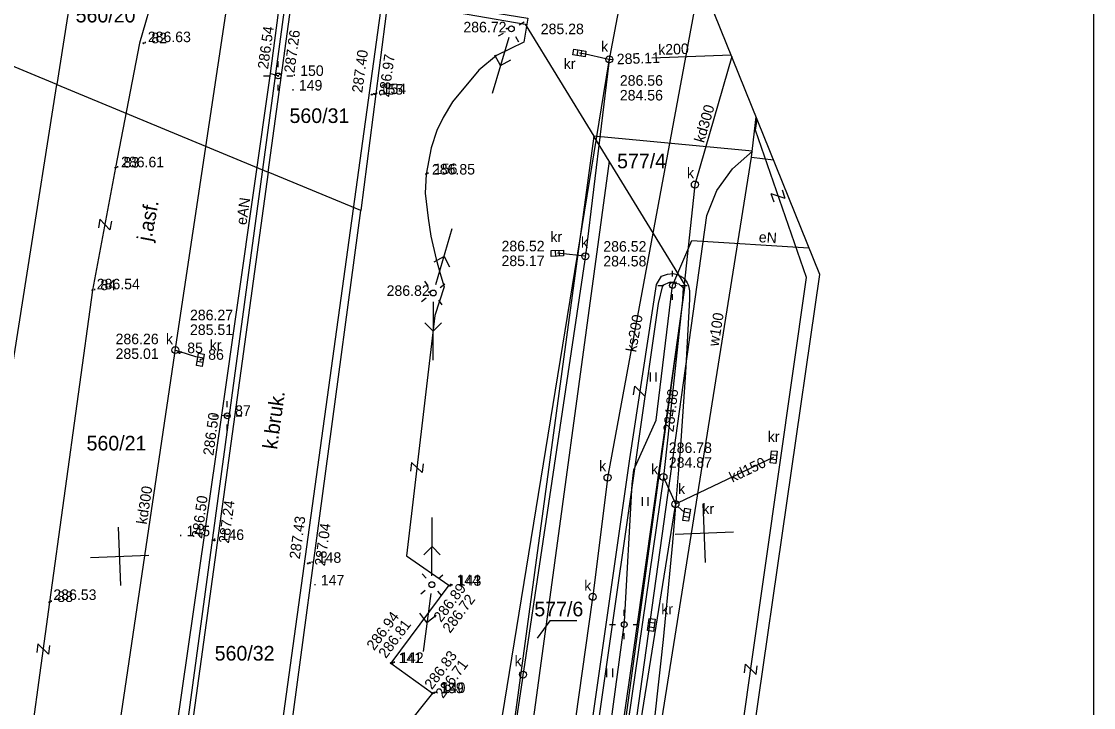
# Model space of a CAD drawing. Extents: x 4632591 to 4651936, y 5351032 to 5369988.
# Drawn here: x 4642775.6 to 4642867.2, y 5360136.4 to 5360195 of the extents above; entities that cross this region are included whole.
import ezdxf

# ---------------------------------------------------------------- set-up
doc = ezdxf.new("R2010")
doc.units = 0
for name, color, linetype in [('EBUPP_312', 7, 'Continuous'), ('EDTTS_991', 7, 'Continuous'), ('EDZPD_211', 7, 'Continuous'), ('EDZPD_219', 7, 'Continuous'), ('SDRPK_422', 7, 'Continuous'), ('SDRPK_423', 7, 'Continuous'), ('SDRPK_432', 7, 'Continuous'), ('SDRPT_450', 7, 'Continuous'), ('SZZTZ_940', 7, 'Continuous'), ('UEEPA_510', 7, 'Continuous'), ('UEEPO_585', 7, 'Continuous'), ('UEETA_515', 7, 'Continuous'), ('UEETA_516', 7, 'Continuous'), ('UKKPA_506', 7, 'Continuous'), ('UKKPA_509', 7, 'Continuous'), ('UKKPO_582', 7, 'Continuous'), ('UWWPO_581', 7, 'Continuous'), ('Warstwa 40', 7, 'Continuous'), ('Warstwa 50', 7, 'Continuous'), ('Warstwa 62', 7, 'Continuous'), ('WUKPS_403', 7, 'Continuous')]:
    doc.layers.add(name, color=color, linetype=linetype)

msp = doc.modelspace()

# ---------------------------------------------------------------- linework, layer by layer
at = {"layer": 'EBUPP_312'}
msp.add_lwpolyline([(4642867.168, 5360325.869), (4642867.168, 5360025.339), (4642701.152, 5360025.339), (4642701.152, 5360349.707), (4642867.168, 5360349.707), (4642867.168, 5360324.166)], dxfattribs=at)
at = {"layer": 'EDTTS_991'}
for p, q in [((4642840.821, 5360179.874), (4642840.576, 5360180.583)), ((4642839.876, 5360179.547), (4642839.631, 5360180.256)), ((4642840.821, 5360179.874), (4642839.631, 5360180.256)), ((4642782.272, 5360178.099), (4642782.133, 5360177.362)), ((4642782.272, 5360178.099), (4642783.116, 5360177.177)), ((4642783.255, 5360177.914), (4642783.116, 5360177.177)), ((4642827.87, 5360163.091), (4642827.983, 5360163.832)), ((4642828.858, 5360162.94), (4642827.983, 5360163.832)), ((4642828.858, 5360162.94), (4642828.972, 5360163.681)), ((4642808.896, 5360157.3), (4642808.808, 5360156.555)), ((4642808.896, 5360157.3), (4642809.801, 5360156.438)), ((4642809.889, 5360157.182), (4642809.801, 5360156.438)), ((4642776.969, 5360141.813), (4642776.868, 5360141.07)), ((4642776.969, 5360141.813), (4642777.859, 5360140.935)), ((4642777.96, 5360141.678), (4642777.859, 5360140.935)), ((4642837.336, 5360139.321), (4642837.442, 5360140.064)), ((4642838.326, 5360139.181), (4642837.442, 5360140.064)), ((4642838.326, 5360139.181), (4642838.432, 5360139.923))]:
    msp.add_line(p, q, dxfattribs=at)
at = {"layer": 'EDZPD_219'}
for p, q in [((4642782.126, 5360212.287), (4642778.595, 5360189.601)), ((4642796.649, 5360182.126), (4642799.275, 5360201.211)), ((4642806.875, 5360196.789), (4642804.574, 5360178.838)), ((4642806.875, 5360196.789), (4642818.602, 5360194.772)), ((4642818.602, 5360194.772), (4642824.477, 5360185.186)), ((4642778.595, 5360189.601), (4642772.763, 5360192.015)), ((4642768.336, 5360124.696), (4642778.595, 5360189.601)), ((4642778.595, 5360189.601), (4642796.649, 5360182.126)), ((4642824.477, 5360185.186), (4642806.059, 5360050.143)), ((4642825.78, 5360183.06), (4642824.477, 5360185.186)), ((4642838.018, 5360183.919), (4642824.477, 5360185.186)), ((4642836.319, 5360182.405), (4642838.018, 5360183.919)), ((4642825.78, 5360183.06), (4642807.62, 5360049.911)), ((4642832.263, 5360172.47), (4642825.78, 5360183.06)), ((4642825.78, 5360183.06), (4642825.78, 5360183.06)), ((4642834.988, 5360180.554), (4642836.319, 5360182.405)), ((4642836.319, 5360182.405), (4642836.319, 5360182.405)), ((4642796.649, 5360182.126), (4642788.376, 5360121.952)), ((4642804.574, 5360178.838), (4642796.649, 5360182.126)), ((4642834.115, 5360178.413), (4642834.988, 5360180.554)), ((4642796.747, 5360120.803), (4642804.574, 5360178.838)), ((4642814.236, 5360035.496), (4642834.115, 5360178.413)), ((4642815.357, 5360048.606), (4642832.263, 5360172.47)), ((4642820.715, 5360143.758), (4642819.624, 5360142.294)), ((4642823.03, 5360143.758), (4642820.715, 5360143.758))]:
    msp.add_line(p, q, dxfattribs=at)
at = {"layer": 'SDRPK_422'}
for points in [[(4642800.957, 5360247.6), (4642789.673, 5360207.012), (4642785.643, 5360193.138), (4642783.61, 5360182.51), (4642781.64, 5360172.03), (4642777.96, 5360145.38), (4642775.66, 5360128.5)], [(4642812.515, 5360206.822), (4642811.234, 5360196.488), (4642818.833, 5360195.279), (4642818.488, 5360193.235), (4642816.156, 5360192.083), (4642814.63, 5360190.846), (4642812.385, 5360188.14), (4642811.608, 5360186.787), (4642811.061, 5360185.664), (4642810.572, 5360184.196), (4642810.14, 5360181.95), (4642810.054, 5360180.31), (4642810.313, 5360178.18), (4642810.543, 5360176.654), (4642811.003, 5360174.668), (4642811.406, 5360173.258), (4642811.694, 5360172.308), (4642810.888, 5360169.861), (4642808.456, 5360149.337), (4642812.07, 5360146.81), (4642807.12, 5360140.16), (4642810.67, 5360137.59), (4642805.721, 5360131.374)], [(4642819.994, 5360030.44), (4642826.832, 5360079.558), (4642831.302, 5360092.86), (4642837.953, 5360140.111), (4642842.636, 5360173.101), (4642838.272, 5360185.712), (4642838.416, 5360186.646)], [(4642818.214, 5360091.65), (4642822.014, 5360118.939), (4642827.541, 5360157.627), (4642829.815, 5360172.509), (4642830.247, 5360173.229), (4642830.765, 5360173.402), (4642831.254, 5360173.459), (4642831.6, 5360173.373)]]:
    msp.add_lwpolyline(points, dxfattribs=at)
msp.add_spline([(4642831.6, 5360173.373), (4642831.894, 5360173.22), (4642832.16, 5360173.036), (4642832.506, 5360172.53), (4642832.639, 5360171.972), (4642832.639, 5360171.253), (4642813.886, 5360039.502)], degree=3, dxfattribs=at)
at = {"layer": 'SDRPK_423'}
for points in [[(4642830.995, 5360172.711), (4642831.721, 5360172.582), (4642832.093, 5360172.223), (4642832.02, 5360170.813), (4642830.77, 5360161.873), (4642827.87, 5360141.308), (4642824.012, 5360114.49), (4642821.192, 5360094.962), (4642818.665, 5360077.403), (4642816.164, 5360058.593), (4642813.583, 5360039.73), (4642813.603, 5360039.77)], [(4642831.571, 5360172.682), (4642830.995, 5360172.711), (4642830.333, 5360172.423), (4642829.959, 5360170.897), (4642819.193, 5360095.651)]]:
    msp.add_lwpolyline(points, dxfattribs=at)
at = {"layer": 'SDRPT_450'}
msp.add_line((4642784.66, 5360097.25), (4642799.288, 5360205.296), dxfattribs=at)
msp.add_lwpolyline([(4642807.866, 5360207.685), (4642795.027, 5360114.592), (4642791.918, 5360092.139)], dxfattribs=at)
at = {"layer": 'SZZTZ_940'}
for p, q in [((4642829.304, 5360164.234), (4642829.304, 5360164.984)), ((4642829.804, 5360164.234), (4642829.804, 5360164.984)), ((4642828.613, 5360153.592), (4642828.613, 5360154.342)), ((4642829.113, 5360153.592), (4642829.113, 5360154.342)), ((4642825.58, 5360138.959), (4642825.58, 5360139.709)), ((4642826.08, 5360138.959), (4642826.08, 5360139.709))]:
    msp.add_line(p, q, dxfattribs=at)
at = {"layer": 'UEEPA_510'}
for centre in [(4642817.423, 5360194.358), (4642797.5, 5360190.34), (4642831.194, 5360172.444), (4642810.744, 5360171.79), (4642793.15, 5360161.29), (4642810.629, 5360146.861), (4642827.07, 5360143.458)]:
    msp.add_circle(centre, 0.25, dxfattribs=at)
at = {"layer": 'UEEPO_585'}
for points in [[(4642796.855, 5360190.558), (4642798.769, 5360205.311), (4642801.706, 5360220.279), (4642802.031, 5360220.279)], [(4642792.696, 5360161.34), (4642796.855, 5360190.558), (4642797.263, 5360190.42)], [(4642797.263, 5360190.42), (4642797.5, 5360190.34)], [(4642831.292, 5360172.674), (4642832.83, 5360176.275), (4642842.851, 5360175.635)], [(4642831.164, 5360172.196), (4642831.194, 5360172.444), (4642831.292, 5360172.674)], [(4642827.084, 5360143.707), (4642827.73, 5360155.453), (4642827.89, 5360156.677), (4642829.806, 5360160.934), (4642831.164, 5360172.196)], [(4642788.363, 5360131.302), (4642792.696, 5360161.34), (4642792.902, 5360161.318)], [(4642792.902, 5360161.318), (4642793.15, 5360161.29)], [(4642825.951, 5360135.166), (4642827.037, 5360143.21)], [(4642827.037, 5360143.21), (4642827.07, 5360143.458), (4642827.084, 5360143.707)]]:
    msp.add_lwpolyline(points, dxfattribs=at)
at = {"layer": 'UEETA_515'}
for p, q in [((4642818.082, 5360194.716), (4642818.521, 5360194.954)), ((4642816.324, 5360193.761), (4642816.764, 5360194)), ((4642817.781, 5360193.699), (4642818.019, 5360193.259)), ((4642797.5, 5360191.09), (4642797.5, 5360191.59)), ((4642796.25, 5360190.34), (4642796.75, 5360190.34)), ((4642798.25, 5360190.34), (4642798.75, 5360190.34)), ((4642797.5, 5360189.09), (4642797.5, 5360189.59)), ((4642831.194, 5360173.194), (4642831.194, 5360173.694)), ((4642809.999, 5360172.793), (4642810.297, 5360172.391)), ((4642811.748, 5360172.535), (4642811.346, 5360172.237)), ((4642829.944, 5360172.444), (4642830.444, 5360172.444)), ((4642831.944, 5360172.444), (4642832.444, 5360172.444)), ((4642831.194, 5360171.194), (4642831.194, 5360171.694)), ((4642810.142, 5360171.342), (4642809.741, 5360171.044)), ((4642811.192, 5360171.188), (4642811.49, 5360170.786)), ((4642793.15, 5360162.04), (4642793.15, 5360162.54)), ((4642791.9, 5360161.29), (4642792.4, 5360161.29)), ((4642793.15, 5360160.04), (4642793.15, 5360160.54)), ((4642793.9, 5360161.29), (4642794.4, 5360161.29)), ((4642809.807, 5360147.803), (4642810.136, 5360147.426)), ((4642811.571, 5360147.683), (4642811.194, 5360147.354)), ((4642810.064, 5360146.368), (4642809.687, 5360146.039)), ((4642811.122, 5360146.296), (4642811.451, 5360145.919)), ((4642827.07, 5360144.208), (4642827.07, 5360144.708)), ((4642825.82, 5360143.458), (4642826.32, 5360143.458)), ((4642827.82, 5360143.458), (4642828.32, 5360143.458)), ((4642827.07, 5360142.208), (4642827.07, 5360142.708))]:
    msp.add_line(p, q, dxfattribs=at)
at = {"layer": 'UEETA_516'}
for p, q in [((4642817.21, 5360193.638), (4642815.791, 5360188.844)), ((4642816.5, 5360191.241), (4642816.023, 5360192.12)), ((4642816.5, 5360191.241), (4642817.379, 5360191.718)), ((4642810.957, 5360172.509), (4642812.376, 5360177.303)), ((4642811.667, 5360174.906), (4642810.788, 5360174.429)), ((4642811.667, 5360174.906), (4642812.144, 5360174.027)), ((4642810.741, 5360171.04), (4642810.718, 5360166.04)), ((4642810.729, 5360168.54), (4642810.026, 5360169.25)), ((4642810.729, 5360168.54), (4642811.44, 5360169.243)), ((4642810.633, 5360147.611), (4642810.656, 5360152.611)), ((4642810.644, 5360150.111), (4642809.934, 5360149.407)), ((4642810.644, 5360150.111), (4642811.348, 5360149.401)), ((4642810.531, 5360146.118), (4642809.876, 5360141.161)), ((4642810.204, 5360143.639), (4642809.595, 5360144.433)), ((4642810.204, 5360143.639), (4642810.997, 5360144.247))]:
    msp.add_line(p, q, dxfattribs=at)
at = {"layer": 'UKKPA_506'}
for centre in [(4642825.785, 5360191.752), (4642833.104, 5360181.057), (4642823.741, 5360174.927), (4642788.709, 5360166.91), (4642825.641, 5360156.015), (4642830.417, 5360156.062), (4642831.442, 5360153.747), (4642824.374, 5360145.825), (4642818.416, 5360139.175)]:
    msp.add_circle(centre, 0.3, dxfattribs=at)
at = {"layer": 'UKKPA_509'}
for p, q in [((4642823.102, 5360192.573), (4642823.027, 5360192.078)), ((4642823.373, 5360192.026), (4642823.448, 5360192.52)), ((4642821.168, 5360175.43), (4642821.186, 5360174.93)), ((4642821.536, 5360174.942), (4642821.518, 5360175.442)), ((4642790.573, 5360165.951), (4642791.066, 5360165.864)), ((4642791.127, 5360166.209), (4642790.634, 5360166.296)), ((4642840.102, 5360157.911), (4642839.605, 5360157.963)), ((4642839.568, 5360157.615), (4642840.066, 5360157.563)), ((4642832.126, 5360152.705), (4642832.621, 5360152.631)), ((4642832.673, 5360152.977), (4642832.178, 5360153.051)), ((4642829.108, 5360143.284), (4642829.603, 5360143.215)), ((4642829.651, 5360143.562), (4642829.156, 5360143.631))]:
    msp.add_line(p, q, dxfattribs=at)
for points in [[(4642822.756, 5360192.625), (4642823.794, 5360192.468), (4642823.719, 5360191.974), (4642822.681, 5360192.131)], [(4642820.819, 5360175.418), (4642821.868, 5360175.454), (4642821.885, 5360174.955), (4642820.836, 5360174.918)], [(4642790.512, 5360165.607), (4642790.695, 5360166.64), (4642791.188, 5360166.553), (4642791.005, 5360165.52)], [(4642839.532, 5360157.267), (4642839.642, 5360158.311), (4642840.139, 5360158.259), (4642840.029, 5360157.215)], [(4642832.074, 5360152.359), (4642832.23, 5360153.397), (4642832.724, 5360153.323), (4642832.569, 5360152.285)], [(4642829.06, 5360142.937), (4642829.205, 5360143.977), (4642829.7, 5360143.908), (4642829.555, 5360142.868)]]:
    msp.add_lwpolyline(points, close=True, dxfattribs=at)
at = {"layer": 'UKKPO_582'}
for p, q in [((4642825.737, 5360191.457), (4642825.785, 5360191.752)), ((4642825.785, 5360191.752), (4642826.084, 5360191.763)), ((4642829.429, 5360191.884), (4642836.208, 5360192.129)), ((4642813.772, 5360117.853), (4642825.737, 5360191.457)), ((4642828.199, 5360169.831), (4642827.577, 5360166.468)), ((4642831.216, 5360163.492), (4642830.784, 5360159.474)), ((4642835.824, 5360155.844), (4642838.674, 5360157.208)), ((4642832.178, 5360153.051), (4642831.659, 5360153.541))]:
    msp.add_line(p, q, dxfattribs=at)
for points in [[(4642828.232, 5360204.706), (4642825.841, 5360192.047)], [(4642788.753, 5360167.207), (4642793.846, 5360201.186)], [(4642833.551, 5360198.727), (4642828.199, 5360169.831)], [(4642823.752, 5360192.189), (4642823.237, 5360192.299)], [(4642825.492, 5360191.815), (4642823.752, 5360192.189)], [(4642825.841, 5360192.047), (4642825.785, 5360191.752), (4642825.492, 5360191.815)], [(4642825.785, 5360191.752), (4642825.749, 5360191.455)], [(4642836.26, 5360191.999), (4642833.187, 5360181.345)], [(4642825.749, 5360191.455), (4642823.777, 5360175.225)], [(4642833.072, 5360180.759), (4642831.216, 5360163.492)], [(4642833.187, 5360181.345), (4642833.104, 5360181.057), (4642833.072, 5360180.759)], [(4642821.879, 5360175.129), (4642821.352, 5360175.186)], [(4642823.443, 5360174.96), (4642821.879, 5360175.129)], [(4642823.777, 5360175.225), (4642823.741, 5360174.927), (4642823.443, 5360174.96)], [(4642823.697, 5360174.631), (4642818.46, 5360139.472)], [(4642823.741, 5360174.927), (4642823.697, 5360174.631)], [(4642788.665, 5360166.614), (4642788.709, 5360166.91), (4642788.995, 5360166.82)], [(4642788.709, 5360166.91), (4642788.753, 5360167.207)], [(4642788.995, 5360166.82), (4642790.522, 5360166.335)], [(4642783.658, 5360132.808), (4642788.665, 5360166.614)], [(4642827.577, 5360166.468), (4642825.696, 5360156.31)], [(4642830.784, 5360159.474), (4642830.449, 5360156.36)], [(4642839.571, 5360157.636), (4642839.835, 5360157.763)], [(4642838.674, 5360157.208), (4642839.571, 5360157.636)], [(4642830.417, 5360156.062), (4642824.969, 5360118.486), (4642816.67, 5360066.46)], [(4642825.696, 5360156.31), (4642825.641, 5360156.015), (4642825.604, 5360155.717)], [(4642830.449, 5360156.36), (4642830.417, 5360156.062), (4642830.539, 5360155.788)], [(4642831.712, 5360153.877), (4642835.824, 5360155.844)], [(4642825.604, 5360155.717), (4642824.411, 5360146.122)], [(4642830.539, 5360155.788), (4642831.32, 5360154.022)], [(4642831.32, 5360154.022), (4642831.442, 5360153.747), (4642831.712, 5360153.877)], [(4642831.394, 5360153.451), (4642823.162, 5360102.03)], [(4642831.442, 5360153.747), (4642831.394, 5360153.451)], [(4642824.411, 5360146.122), (4642824.374, 5360145.825), (4642824.332, 5360145.528)], [(4642824.332, 5360145.528), (4642820.329, 5360117.221)], [(4642818.46, 5360139.472), (4642818.416, 5360139.175), (4642818.371, 5360138.879)], [(4642818.371, 5360138.879), (4642813.135, 5360103.864)]]:
    msp.add_lwpolyline(points, dxfattribs=at)
at = {"layer": 'UWWPO_581'}
msp.add_line((4642837.938, 5360183.405), (4642838.333, 5360186.852), dxfattribs=at)
msp.add_lwpolyline([(4642820.219, 5360068.578), (4642825.461, 5360105.053), (4642832.804, 5360151.24), (4642837.938, 5360183.405), (4642839.815, 5360183.173)], dxfattribs=at)
at = {"layer": 'Warstwa 40'}
for p, q in [((4642843.767, 5360173.362), (4642822.748, 5360225.547)), ((4642823.333, 5360031.534), (4642843.767, 5360173.362))]:
    msp.add_line(p, q, dxfattribs=at)
at = {"layer": 'Warstwa 50'}
for p, q in [((4642834.013, 5360148.771), (4642833.815, 5360153.767)), ((4642784.053, 5360146.792), (4642783.855, 5360151.788)), ((4642831.416, 5360151.17), (4642836.412, 5360151.368)), ((4642781.456, 5360149.191), (4642786.452, 5360149.389))]:
    msp.add_line(p, q, dxfattribs=at)
at = {"layer": 'WUKPS_403'}
for centre in [(4642817.047, 5360194.384), (4642785.99, 5360193.13), (4642797.5, 5360190.34), (4642797.63, 5360190.5), (4642805.75, 5360188.79), (4642805.5, 5360188.74), (4642783.61, 5360182.51), (4642810.14, 5360181.95), (4642781.64, 5360172.03), (4642810.409, 5360171.863), (4642789.06, 5360166.65), (4642790.85, 5360166.08), (4642793.15, 5360161.29), (4642791.91, 5360150.68), (4642792.04, 5360150.64), (4642800.03, 5360148.68), (4642800.21, 5360148.73), (4642812.07, 5360146.81), (4642812.18, 5360146.77), (4642777.96, 5360145.38), (4642807.12, 5360140.16), (4642807.25, 5360140.17), (4642810.67, 5360137.59), (4642810.82, 5360137.61)]:
    msp.add_circle(centre, 0.045, dxfattribs=at)

# ---------------------------------------------------------------- texts
at = {"layer": 'EDZPD_211'}
for s, p in [('560/20', (4642780.191, 5360194.911)), ('560/31', (4642798.467, 5360186.319)), ('577/4', (4642826.456, 5360182.449)), ('560/21', (4642781.126, 5360158.334)), ('577/6', (4642819.385, 5360144.157)), ('560/32', (4642792.072, 5360140.377))]:
    msp.add_text(s, height=1.25, dxfattribs=at).set_placement(p)
at = {"layer": 'SDRPK_432'}
for s, rotation, p in [('j.asf.', 79.35394, (4642786.651, 5360176.146)), ('k.bruk.', 82.13796, (4642797.399, 5360158.374))]:
    msp.add_text(s, height=1.25, rotation=rotation, dxfattribs=at).set_placement(p)
at = {"layer": 'UEEPO_585'}
for s, rotation, p in [('eAN', 81.89921, (4642794.778, 5360177.559)), ('eN', 356.34172, (4642838.545, 5360176.136))]:
    msp.add_text(s, height=0.9, rotation=rotation, dxfattribs=at).set_placement(p)
at = {"layer": 'UKKPA_506'}
for s, p in [('k', (4642825.094, 5360192.4)), ('kr', (4642821.901, 5360190.937)), ('286.56', (4642826.691, 5360189.502)), ('284.56', (4642826.691, 5360188.242)), ('k', (4642832.426, 5360181.603)), ('kr', (4642820.757, 5360176.144)), ('k', (4642823.367, 5360175.676)), ('286.52', (4642825.281, 5360175.321)), ('284.58', (4642825.281, 5360174.061)), ('286.26', (4642783.605, 5360167.413)), ('k', (4642787.903, 5360167.414)), ('kr', (4642791.652, 5360166.886)), ('285.01', (4642783.605, 5360166.153)), ('kr', (4642839.328, 5360159.064)), ('286.78', (4642830.875, 5360158.114)), ('284.87', (4642830.875, 5360156.854)), ('k', (4642824.921, 5360156.562)), ('k', (4642829.364, 5360156.285)), ('k', (4642831.668, 5360154.612)), ('kr', (4642833.741, 5360152.892)), ('k', (4642823.655, 5360146.343)), ('kr', (4642830.229, 5360144.325)), ('k', (4642817.696, 5360139.895))]:
    msp.add_text(s, height=0.9, dxfattribs=at).set_placement(p)
at = {"layer": 'UKKPA_509'}
for s, p in [('285.28', (4642819.934, 5360193.909)), ('286.52', (4642816.581, 5360175.348)), ('285.17', (4642816.581, 5360174.088)), ('286.27', (4642789.963, 5360169.461)), ('285.51', (4642789.963, 5360168.201))]:
    msp.add_text(s, height=0.9, dxfattribs=at).set_placement(p)
at = {"layer": 'UKKPO_582'}
for s, rotation, p in [('k200', 2.06232, (4642829.988, 5360192.13)), ('285.11', 2.06232, (4642826.446, 5360191.327)), ('285.11', 2.06232, (4642826.446, 5360191.326)), ('kd300', 73.90768, (4642833.884, 5360184.573)), ('ks200', 79.5074, (4642828.076, 5360166.691)), ('284.88', 83.86197, (4642831.28, 5360159.874)), ('kd150', 25.5637, (4642836.311, 5360155.578)), ('kd300', 81.57616, (4642786.27, 5360151.978))]:
    msp.add_text(s, height=0.9, rotation=rotation, dxfattribs=at).set_placement(p)
at = {"layer": 'UWWPO_581'}
msp.add_text('w100', height=0.9, rotation=80.93152, dxfattribs=at).set_placement((4642835.122, 5360167.19))
at = {"layer": 'Warstwa 62'}
for s, p in [('. 82', (4642785.99, 5360193.13)), ('. 150', (4642798.708, 5360190.34)), ('. 149', (4642798.596, 5360189.095)), ('. 155', (4642805.5, 5360188.74)), ('. 154', (4642805.75, 5360188.79)), ('. 83', (4642783.61, 5360182.51)), ('. 156', (4642810.14, 5360181.95)), ('. 84', (4642781.64, 5360172.03)), ('. 85', (4642789.06, 5360166.65)), ('. 86', (4642790.85, 5360166.08)), ('. 87', (4642793.15, 5360161.29)), ('. 145', (4642789, 5360151)), ('. 146', (4642791.91, 5360150.68)), ('. 148', (4642800.21, 5360148.73)), ('. 147', (4642800.469, 5360146.792)), ('. 144', (4642812.07, 5360146.81)), ('. 143', (4642812.18, 5360146.77)), ('. 88', (4642777.96, 5360145.38)), ('. 141', (4642807.12, 5360140.16)), ('. 142', (4642807.25, 5360140.17)), ('. 139', (4642810.67, 5360137.59)), ('. 140', (4642810.82, 5360137.61))]:
    msp.add_text(s, height=0.9, dxfattribs=at).set_placement(p)
at = {"layer": 'WUKPS_403'}
for s, rotation, p in [('286.54', 82.14789, (4642796.628, 5360190.879)), ('287.26', 82.14789, (4642798.876, 5360190.559)), ('287.40', 82.14789, (4642804.676, 5360188.857)), ('286.97', 82.14789, (4642806.964, 5360188.484)), ('286.50', 82.28998, (4642791.959, 5360157.855)), ('286.50', 82.28998, (4642790.987, 5360150.765)), ('287.24', 82.28998, (4642793.289, 5360150.352)), ('287.43', 82.28998, (4642799.341, 5360149.009)), ('287.04', 82.28998, (4642801.496, 5360148.41)), ('286.89', 53.33744, (4642811.413, 5360143.588)), ('286.72', 53.33744, (4642812.185, 5360142.657)), ('286.94', 53.33744, (4642805.693, 5360141.18)), ('286.81', 53.33744, (4642806.704, 5360140.502)), ('286.83', 53.33744, (4642810.635, 5360137.841)), ('286.71', 53.33744, (4642811.58, 5360137.083))]:
    msp.add_text(s, height=0.9, rotation=rotation, dxfattribs=at).set_placement(p)
for s, p in [('286.72', (4642813.322, 5360194.064)), ('286.63', (4642786.358, 5360193.226)), ('286.61', (4642784.07, 5360182.531)), ('286.85', (4642810.635, 5360181.913)), ('286.54', (4642781.995, 5360172.102)), ('286.82', (4642806.764, 5360171.543)), ('286.53', (4642778.29, 5360145.557))]:
    msp.add_text(s, height=0.9, dxfattribs=at).set_placement(p)

doc.saveas('drawing.dxf')
